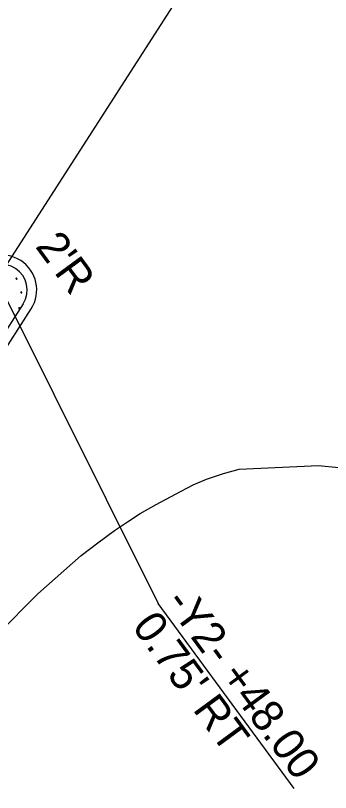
# Model space of a CAD drawing. Extents: x 1763480 to 1764420, y 711010 to 712012.
# Drawn here: x 1763830.2 to 1763855, y 711369.7 to 711430.8 of the extents above; entities that cross this region are included whole.
import ezdxf

# ---------------------------------------------------------------- set-up
doc = ezdxf.new("R2010")
doc.units = 0
for name, color, linetype in [('Old_Level_10', 7, 'Continuous'), ('Prop Conc Island Cover', 7, 'Continuous'), ('Prop EOT', 7, 'Continuous'), ('Prop Grid Mask', 7, 'Continuous'), ('Prop Lane Lines', 7, 'Continuous'), ('Sheet Block Revision CELL', 7, 'Continuous')]:
    doc.layers.add(name, color=color, linetype=linetype)

msp = doc.modelspace()

# ---------------------------------------------------------------- linework, layer by layer
at = {"layer": 'Old_Level_10'}
for points in [[(1763830.261, 711410.198), (1763830.234, 711410.198), (1763830.23, 711410.121), (1763830.31, 711410.09), (1763830.331, 711410.154), (1763830.295, 711410.177), (1763830.272, 711410.186), (1763830.26, 711410.189)], [(1763830.637, 711409.12), (1763830.611, 711409.121), (1763830.609, 711409.043), (1763830.688, 711409.014), (1763830.708, 711409.076), (1763830.672, 711409.099), (1763830.649, 711409.108), (1763830.636, 711409.111)], [(1763830.475, 711407.882), (1763830.449, 711407.882), (1763830.445, 711407.804), (1763830.525, 711407.776), (1763830.545, 711407.838), (1763830.51, 711407.861), (1763830.487, 711407.869), (1763830.474, 711407.873)]]:
    msp.add_open_spline(points, degree=3, dxfattribs=at)
at = {"layer": 'Prop Conc Island Cover'}
msp.add_line((1763830.806, 711408.185), (1763805.942, 711369.484), dxfattribs=at)
for start, end in [(57.28041, 145.41273), (327.28041, 57.28041)]:
    msp.add_arc((1763829.123, 711409.266), 2, start, end, dxfattribs=at)
at = {"layer": 'Prop EOT'}
for p, q in [((1763846.563, 711394.824), (1763847.816, 711395.178)), ((1763847.816, 711395.178), (1763854.033, 711395.451)), ((1763854.033, 711395.451), (1763855.637, 711395.317)), ((1763844.178, 711393.951), (1763845.222, 711394.389)), ((1763845.222, 711394.389), (1763846.563, 711394.824)), ((1763842.791, 711393.217), (1763844.178, 711393.951)), ((1763841.267, 711392.393), (1763842.791, 711393.217)), ((1763840.014, 711391.699), (1763841.267, 711392.393)), ((1763839.027, 711391.045), (1763840.014, 711391.699)), ((1763837.986, 711390.346), (1763839.027, 711391.045)), ((1763836.694, 711389.375), (1763837.986, 711390.346)), ((1763835.375, 711388.389), (1763836.694, 711389.375)), ((1763831.962, 711385.374), (1763835.375, 711388.389)), ((1763827.651, 711381.057), (1763831.962, 711385.374))]:
    msp.add_line(p, q, dxfattribs=at)
at = {"layer": 'Prop Grid Mask'}
for p in [(1763829.123, 711409.266), (1763852.123, 711370.063)]:
    msp.add_line(p, (1763841.422, 711384.617), dxfattribs=at)
at = {"layer": 'Prop Lane Lines'}
for p in [(1763805.492, 711367.396), (1763806.573, 711369.079)]:
    msp.add_line(p, (1763831.437, 711407.78), dxfattribs=at)
msp.add_arc((1763829.123, 711409.266), 2.75, 327.28041, 147.28041, dxfattribs=at)
at = {"layer": 'Sheet Block Revision CELL'}
msp.add_line((1763783.028, 711338.906), (1763848.854, 711441.364), dxfattribs=at)

# ---------------------------------------------------------------- texts
at = {"layer": 'Prop Grid Mask'}
for s, p in [("2'R", (1763831.706, 711412.684)), ('-Y2- +48.00', (1763841.931, 711384.709)), ("0.75' RT", (1763839.313, 711382.784))]:
    msp.add_text(s, height=2.5, rotation=306.32498, dxfattribs=at).set_placement(p)

doc.saveas('drawing.dxf')
